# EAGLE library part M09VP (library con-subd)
SUB-D
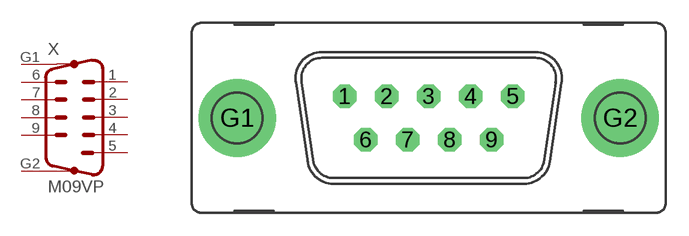
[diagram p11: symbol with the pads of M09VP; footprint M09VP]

Designator prefix X

## M09VP (OC_FARNELL: unknown; OC_NEWARK: unknown)  [M09VP]
1  1  pas
2  2  pas
3  3  pas
4  4  pas
5  5  pas
6  6  pas
7  7  pas
8  8  pas
9  9  pas
G1  G1  pas
G2  G2  pas

## Footprint M09VP (pad centres in mm)
SUB-D
drill 1.016 octagon: 1 -5.486,1.422; 2 -2.743,1.422; 3 0,1.422; 4 2.743,1.422; 5 5.486,1.422; 6 -4.115,-1.422; 7 -1.372,-1.422; 8 1.372,-1.422; 9 4.115,-1.422
drill 3.302 pad 5.08 round: G1 -12.522,0; G2 12.522,0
